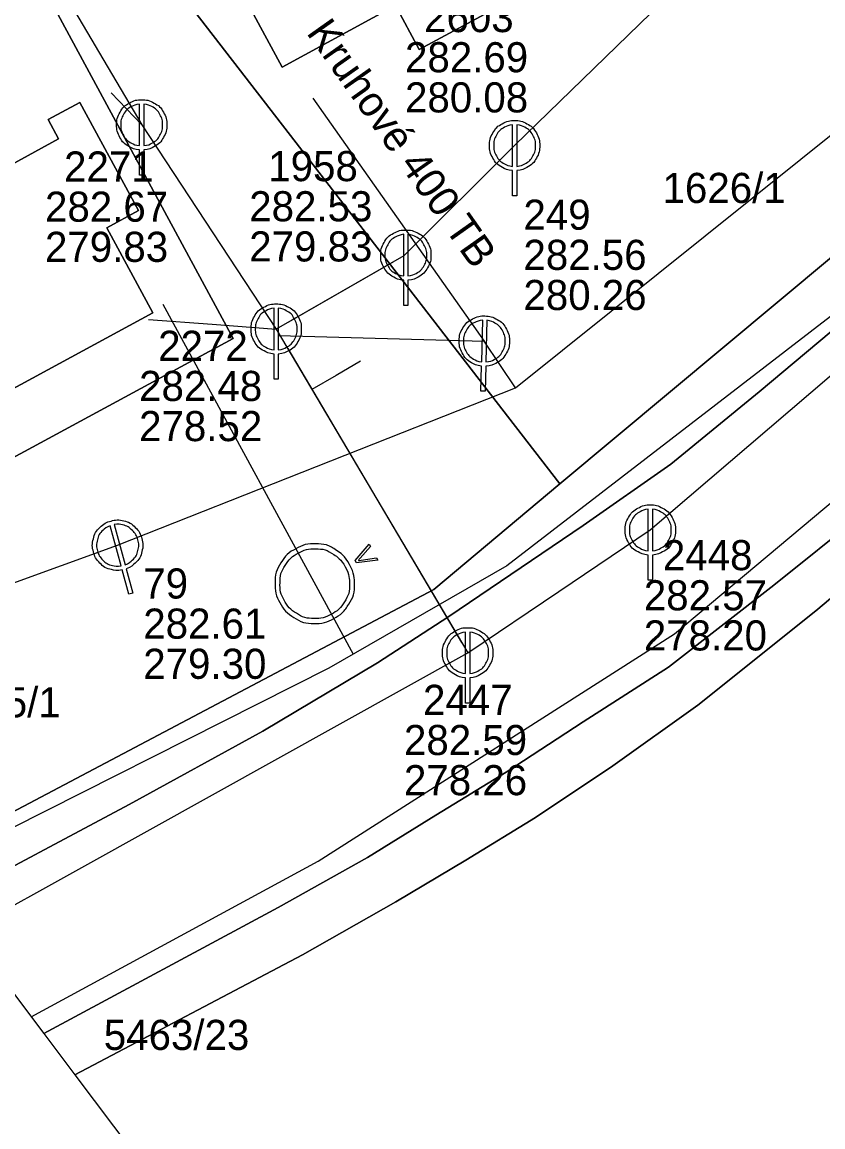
# Model space of a CAD drawing. Extents: x -570698 to -570232, y -1086952 to -1086596.
# Drawn here: x -570540.7 to -570500.8, y -1086880.7 to -1086825.7 of the extents above; entities that cross this region are included whole.
import ezdxf

# ---------------------------------------------------------------- set-up
doc = ezdxf.new("R2010")
doc.units = 0
for name, color, linetype in [('Chránička - kanalizace', 7, 'Continuous'), ('Default', 7, 'Continuous'), ('Kanalizační přípojka', 7, 'Continuous'), ('Kanalizační stoka', 7, 'Continuous'), ('Kanalizační šachta', 7, 'Continuous'), ('Parcela-polygon', 7, 'Continuous'), ('Parcela-text', 7, 'Continuous'), ('Popis kmenové stoky', 7, 'Continuous'), ('Popis šachty', 7, 'Continuous'), ('Vodovodní přípojka', 7, 'Continuous'), ('Vodovodní řad', 7, 'Continuous'), ('Vodovodní šachta', 7, 'Continuous')]:
    doc.layers.add(name, color=color, linetype=linetype)

msp = doc.modelspace()

# ---------------------------------------------------------------- linework, layer by layer
at = {"layer": 'Chránička - kanalizace'}
for points in [[(-570522.159, -1086837.647), (-570527.394, -1086840.643)], [(-570527.425, -1086841.962), (-570518.762, -1086856.609)]]:
    msp.add_lwpolyline(points, dxfattribs=at)
at = {"layer": 'Default'}
for points in [[(-570534.803, -1086832.068), (-570535.061, -1086832.05), (-570535.323, -1086831.904), (-570535.62, -1086831.74), (-570535.785, -1086831.443), (-570535.95, -1086831.145), (-570535.95, -1086830.82), (-570535.95, -1086830.493), (-570535.782, -1086830.193), (-570535.613, -1086829.892), (-570535.315, -1086829.731), (-570535.017, -1086829.57), (-570534.7, -1086829.57), (-570534.385, -1086829.57), (-570534.086, -1086829.731), (-570533.787, -1086829.892), (-570533.618, -1086830.193), (-570533.45, -1086830.493), (-570533.45, -1086830.82), (-570533.45, -1086831.145), (-570533.615, -1086831.443), (-570533.78, -1086831.74), (-570534.077, -1086831.904), (-570534.339, -1086832.05), (-570534.597, -1086832.068)], [(-570534.803, -1086829.782), (-570535, -1086829.799), (-570535.215, -1086829.914), (-570535.464, -1086830.049), (-570535.603, -1086830.299), (-570535.742, -1086830.549), (-570535.742, -1086830.82), (-570535.742, -1086831.091), (-570535.606, -1086831.338), (-570535.469, -1086831.584), (-570535.22, -1086831.721), (-570535.008, -1086831.841), (-570534.803, -1086831.855)], [(-570534.597, -1086831.855), (-570534.392, -1086831.841), (-570534.178, -1086831.721), (-570533.931, -1086831.584), (-570533.794, -1086831.338), (-570533.658, -1086831.091), (-570533.658, -1086830.82), (-570533.658, -1086830.549), (-570533.798, -1086830.299), (-570533.938, -1086830.049), (-570534.187, -1086829.914), (-570534.4, -1086829.799), (-570534.597, -1086829.782)], [(-570516.223, -1086833.098), (-570516.481, -1086833.08), (-570516.743, -1086832.934), (-570517.04, -1086832.77), (-570517.205, -1086832.473), (-570517.37, -1086832.175), (-570517.37, -1086831.85), (-570517.37, -1086831.523), (-570517.202, -1086831.223), (-570517.033, -1086830.922), (-570516.735, -1086830.761), (-570516.437, -1086830.6), (-570516.12, -1086830.6), (-570515.805, -1086830.6), (-570515.506, -1086830.761), (-570515.207, -1086830.922), (-570515.038, -1086831.223), (-570514.87, -1086831.523), (-570514.87, -1086831.85), (-570514.87, -1086832.175), (-570515.035, -1086832.473), (-570515.2, -1086832.77), (-570515.497, -1086832.934), (-570515.759, -1086833.08), (-570516.017, -1086833.098)], [(-570516.223, -1086830.812), (-570516.42, -1086830.829), (-570516.635, -1086830.944), (-570516.884, -1086831.079), (-570517.023, -1086831.329), (-570517.162, -1086831.579), (-570517.162, -1086831.85), (-570517.162, -1086832.121), (-570517.026, -1086832.368), (-570516.889, -1086832.614), (-570516.64, -1086832.751), (-570516.428, -1086832.871), (-570516.223, -1086832.885)], [(-570516.017, -1086832.885), (-570515.812, -1086832.871), (-570515.598, -1086832.751), (-570515.351, -1086832.614), (-570515.214, -1086832.368), (-570515.078, -1086832.121), (-570515.078, -1086831.85), (-570515.078, -1086831.579), (-570515.218, -1086831.329), (-570515.358, -1086831.079), (-570515.607, -1086830.944), (-570515.82, -1086830.829), (-570516.017, -1086830.812)], [(-570521.643, -1086838.558), (-570521.901, -1086838.54), (-570522.163, -1086838.394), (-570522.46, -1086838.23), (-570522.625, -1086837.933), (-570522.79, -1086837.635), (-570522.79, -1086837.31), (-570522.79, -1086836.983), (-570522.622, -1086836.683), (-570522.453, -1086836.382), (-570522.155, -1086836.221), (-570521.857, -1086836.06), (-570521.54, -1086836.06), (-570521.225, -1086836.06), (-570520.926, -1086836.221), (-570520.627, -1086836.382), (-570520.458, -1086836.683), (-570520.29, -1086836.983), (-570520.29, -1086837.31), (-570520.29, -1086837.635), (-570520.455, -1086837.933), (-570520.62, -1086838.23), (-570520.917, -1086838.394), (-570521.179, -1086838.54), (-570521.437, -1086838.558)], [(-570521.643, -1086836.272), (-570521.84, -1086836.289), (-570522.055, -1086836.404), (-570522.304, -1086836.539), (-570522.443, -1086836.789), (-570522.582, -1086837.039), (-570522.582, -1086837.31), (-570522.582, -1086837.581), (-570522.446, -1086837.828), (-570522.309, -1086838.074), (-570522.06, -1086838.211), (-570521.848, -1086838.331), (-570521.643, -1086838.345)], [(-570521.437, -1086838.345), (-570521.232, -1086838.331), (-570521.018, -1086838.211), (-570520.771, -1086838.074), (-570520.634, -1086837.828), (-570520.498, -1086837.581), (-570520.498, -1086837.31), (-570520.498, -1086837.039), (-570520.638, -1086836.789), (-570520.778, -1086836.539), (-570521.027, -1086836.404), (-570521.24, -1086836.289), (-570521.437, -1086836.272)], [(-570528.103, -1086842.238), (-570528.361, -1086842.22), (-570528.623, -1086842.074), (-570528.92, -1086841.91), (-570529.085, -1086841.613), (-570529.25, -1086841.315), (-570529.25, -1086840.99), (-570529.25, -1086840.663), (-570529.082, -1086840.363), (-570528.913, -1086840.062), (-570528.615, -1086839.901), (-570528.317, -1086839.74), (-570528, -1086839.74), (-570527.685, -1086839.74), (-570527.386, -1086839.901), (-570527.087, -1086840.062), (-570526.918, -1086840.363), (-570526.75, -1086840.663), (-570526.75, -1086840.99), (-570526.75, -1086841.315), (-570526.915, -1086841.613), (-570527.08, -1086841.91), (-570527.377, -1086842.074), (-570527.639, -1086842.22), (-570527.897, -1086842.238)], [(-570528.103, -1086839.952), (-570528.3, -1086839.969), (-570528.515, -1086840.084), (-570528.764, -1086840.219), (-570528.903, -1086840.469), (-570529.042, -1086840.719), (-570529.042, -1086840.99), (-570529.042, -1086841.261), (-570528.906, -1086841.508), (-570528.769, -1086841.754), (-570528.52, -1086841.891), (-570528.308, -1086842.011), (-570528.103, -1086842.025)], [(-570527.897, -1086842.025), (-570527.692, -1086842.011), (-570527.478, -1086841.891), (-570527.231, -1086841.754), (-570527.094, -1086841.508), (-570526.958, -1086841.261), (-570526.958, -1086840.99), (-570526.958, -1086840.719), (-570527.098, -1086840.469), (-570527.238, -1086840.219), (-570527.487, -1086840.084), (-570527.7, -1086839.969), (-570527.897, -1086839.952)], [(-570517.766, -1086842.834), (-570518.024, -1086842.81), (-570518.281, -1086842.657), (-570518.575, -1086842.485), (-570518.732, -1086842.183), (-570518.888, -1086841.881), (-570518.88, -1086841.556), (-570518.871, -1086841.229), (-570518.695, -1086840.934), (-570518.518, -1086840.638), (-570518.216, -1086840.485), (-570517.914, -1086840.332), (-570517.597, -1086840.34), (-570517.282, -1086840.348), (-570516.987, -1086840.518), (-570516.693, -1086840.687), (-570516.532, -1086840.991), (-570516.372, -1086841.296), (-570516.381, -1086841.623), (-570516.389, -1086841.948), (-570516.562, -1086842.241), (-570516.735, -1086842.534), (-570517.037, -1086842.69), (-570517.302, -1086842.829), (-570517.561, -1086842.839)], [(-570517.705, -1086840.55), (-570517.903, -1086840.561), (-570518.121, -1086840.67), (-570518.373, -1086840.798), (-570518.519, -1086841.044), (-570518.665, -1086841.291), (-570518.672, -1086841.562), (-570518.679, -1086841.833), (-570518.549, -1086842.083), (-570518.419, -1086842.333), (-570518.174, -1086842.476), (-570517.965, -1086842.602), (-570517.76, -1086842.622)], [(-570517.555, -1086842.627), (-570517.35, -1086842.618), (-570517.132, -1086842.504), (-570516.882, -1086842.374), (-570516.739, -1086842.131), (-570516.595, -1086841.888), (-570516.588, -1086841.617), (-570516.581, -1086841.347), (-570516.714, -1086841.093), (-570516.848, -1086840.839), (-570517.093, -1086840.698), (-570517.303, -1086840.578), (-570517.5, -1086840.555)], [(-570509.463, -1086852.248), (-570509.721, -1086852.23), (-570509.983, -1086852.084), (-570510.28, -1086851.92), (-570510.445, -1086851.623), (-570510.61, -1086851.325), (-570510.61, -1086851), (-570510.61, -1086850.673), (-570510.442, -1086850.373), (-570510.273, -1086850.072), (-570509.975, -1086849.911), (-570509.677, -1086849.75), (-570509.36, -1086849.75), (-570509.045, -1086849.75), (-570508.746, -1086849.911), (-570508.447, -1086850.072), (-570508.278, -1086850.373), (-570508.11, -1086850.673), (-570508.11, -1086851), (-570508.11, -1086851.325), (-570508.275, -1086851.623), (-570508.44, -1086851.92), (-570508.737, -1086852.084), (-570508.999, -1086852.23), (-570509.257, -1086852.248)], [(-570509.463, -1086849.962), (-570509.66, -1086849.979), (-570509.875, -1086850.094), (-570510.124, -1086850.229), (-570510.263, -1086850.479), (-570510.402, -1086850.729), (-570510.402, -1086851), (-570510.402, -1086851.271), (-570510.266, -1086851.518), (-570510.129, -1086851.764), (-570509.88, -1086851.901), (-570509.668, -1086852.021), (-570509.463, -1086852.035)], [(-570509.257, -1086852.035), (-570509.052, -1086852.021), (-570508.838, -1086851.901), (-570508.591, -1086851.764), (-570508.454, -1086851.518), (-570508.318, -1086851.271), (-570508.318, -1086851), (-570508.318, -1086850.729), (-570508.458, -1086850.479), (-570508.598, -1086850.229), (-570508.847, -1086850.094), (-570509.06, -1086849.979), (-570509.257, -1086849.962)], [(-570535.671, -1086852.99), (-570535.925, -1086853.042), (-570536.216, -1086852.969), (-570536.546, -1086852.89), (-570536.783, -1086852.646), (-570537.021, -1086852.402), (-570537.106, -1086852.088), (-570537.192, -1086851.773), (-570537.109, -1086851.439), (-570537.025, -1086851.105), (-570536.78, -1086850.871), (-570536.535, -1086850.637), (-570536.229, -1086850.554), (-570535.925, -1086850.471), (-570535.594, -1086850.548), (-570535.263, -1086850.625), (-570535.021, -1086850.87), (-570534.78, -1086851.116), (-570534.694, -1086851.431), (-570534.609, -1086851.744), (-570534.689, -1086852.075), (-570534.77, -1086852.406), (-570535.014, -1086852.642), (-570535.228, -1086852.852), (-570535.473, -1086852.936)], [(-570536.272, -1086850.786), (-570536.458, -1086850.854), (-570536.635, -1086851.021), (-570536.84, -1086851.216), (-570536.909, -1086851.494), (-570536.977, -1086851.772), (-570536.906, -1086852.034), (-570536.835, -1086852.295), (-570536.638, -1086852.497), (-570536.441, -1086852.699), (-570536.165, -1086852.766), (-570535.929, -1086852.825), (-570535.727, -1086852.785)], [(-570535.529, -1086852.732), (-570535.335, -1086852.664), (-570535.159, -1086852.492), (-570534.957, -1086852.295), (-570534.89, -1086852.021), (-570534.823, -1086851.747), (-570534.894, -1086851.486), (-570534.965, -1086851.224), (-570535.167, -1086851.02), (-570535.368, -1086850.815), (-570535.643, -1086850.751), (-570535.879, -1086850.696), (-570536.074, -1086850.732)], [(-570524.34, -1086852.724), (-570524.101, -1086853.162), (-570524.099, -1086853.7), (-570524.096, -1086854.237), (-570524.387, -1086854.701), (-570524.677, -1086855.164), (-570525.134, -1086855.412), (-570525.584, -1086855.657), (-570526.122, -1086855.652), (-570526.66, -1086855.647), (-570527.115, -1086855.358), (-570527.57, -1086855.068), (-570527.817, -1086854.615), (-570528.06, -1086854.168), (-570528.056, -1086853.628), (-570528.051, -1086853.089), (-570527.763, -1086852.635), (-570527.475, -1086852.18), (-570527.025, -1086851.935), (-570526.569, -1086851.687), (-570526.023, -1086851.692), (-570525.478, -1086851.697), (-570525.028, -1086851.991), (-570524.578, -1086852.285), (-570524.34, -1086852.724)], [(-570524.556, -1086852.841), (-570524.763, -1086852.46), (-570525.158, -1086852.202), (-570525.553, -1086851.944), (-570526.031, -1086851.939), (-570526.508, -1086851.934), (-570526.907, -1086852.152), (-570527.301, -1086852.366), (-570527.553, -1086852.764), (-570527.806, -1086853.162), (-570527.81, -1086853.633), (-570527.814, -1086854.104), (-570527.6, -1086854.497), (-570527.383, -1086854.897), (-570526.985, -1086855.149), (-570526.587, -1086855.401), (-570526.116, -1086855.406), (-570525.645, -1086855.41), (-570525.251, -1086855.196), (-570524.852, -1086854.979), (-570524.599, -1086854.573), (-570524.345, -1086854.166), (-570524.346, -1086853.696), (-570524.347, -1086853.226), (-570524.556, -1086852.841)], [(-570523.82, -1086852.406), (-570523.883, -1086852.476), (-570523.939, -1086852.529), (-570523.856, -1086852.511), (-570523.769, -1086852.499)], [(-570518.563, -1086858.368), (-570518.821, -1086858.35), (-570519.083, -1086858.204), (-570519.38, -1086858.04), (-570519.545, -1086857.743), (-570519.71, -1086857.445), (-570519.71, -1086857.12), (-570519.71, -1086856.793), (-570519.542, -1086856.493), (-570519.373, -1086856.192), (-570519.075, -1086856.031), (-570518.777, -1086855.87), (-570518.46, -1086855.87), (-570518.145, -1086855.87), (-570517.846, -1086856.031), (-570517.547, -1086856.192), (-570517.378, -1086856.493), (-570517.21, -1086856.793), (-570517.21, -1086857.12), (-570517.21, -1086857.445), (-570517.375, -1086857.743), (-570517.54, -1086858.04), (-570517.837, -1086858.204), (-570518.099, -1086858.35), (-570518.357, -1086858.368)], [(-570518.563, -1086856.082), (-570518.76, -1086856.099), (-570518.975, -1086856.214), (-570519.224, -1086856.349), (-570519.363, -1086856.599), (-570519.502, -1086856.849), (-570519.502, -1086857.12), (-570519.502, -1086857.391), (-570519.366, -1086857.638), (-570519.229, -1086857.884), (-570518.98, -1086858.021), (-570518.768, -1086858.141), (-570518.563, -1086858.155)], [(-570518.357, -1086858.155), (-570518.152, -1086858.141), (-570517.938, -1086858.021), (-570517.691, -1086857.884), (-570517.554, -1086857.638), (-570517.418, -1086857.391), (-570517.418, -1086857.12), (-570517.418, -1086856.849), (-570517.558, -1086856.599), (-570517.698, -1086856.349), (-570517.947, -1086856.214), (-570518.16, -1086856.099), (-570518.357, -1086856.082)]]:
    msp.add_open_spline(points, degree=3, dxfattribs=at)
at = {"layer": 'Kanalizační přípojka'}
msp.add_line((-570527.889, -1086841.316), (-570517.63, -1086841.59), dxfattribs=at)
for points in [[(-570536.216, -1086829.226), (-570534.7, -1086830.82)], [(-570534.368, -1086840.516), (-570531.184, -1086840.753), (-570528, -1086840.99)], [(-570523.8, -1086842.59), (-570525.009, -1086843.296), (-570526.218, -1086844.003)]]:
    msp.add_lwpolyline(points, dxfattribs=at)
at = {"layer": 'Kanalizační stoka'}
for p, q in [((-570516.073, -1086843.915), (-570416.01, -1086763.66)), ((-570535.9, -1086851.76), (-570516.073, -1086843.915))]:
    msp.add_line(p, q, dxfattribs=at)
for points in [[(-570500.84, -1086817), (-570516.12, -1086831.85)], [(-570539.34, -1086822.925), (-570534.7, -1086830.82)], [(-570509.36, -1086851), (-570496.445, -1086839.955), (-570483.53, -1086828.91)], [(-570526.18, -1086829.489), (-570517.63, -1086841.59)], [(-570534.7, -1086830.82), (-570528, -1086840.99)], [(-570516.12, -1086831.85), (-570521.64, -1086837.35)], [(-570521.64, -1086837.35), (-570528, -1086840.99)], [(-570528, -1086840.99), (-570518.46, -1086857.12)], [(-570516.073, -1086843.915), (-570517.63, -1086841.59)], [(-570518.46, -1086857.12), (-570513.91, -1086854.06), (-570509.36, -1086851)], [(-570553.189, -1086858.005), (-570553.028, -1086857.971), (-570535.9, -1086851.76)], [(-570543.41, -1086870.991), (-570537.535, -1086867.725), (-570518.46, -1086857.12)]]:
    msp.add_lwpolyline(points, dxfattribs=at)
at = {"layer": 'Kanalizační šachta'}
for points in [[(-570534.803, -1086831.855), (-570534.803, -1086829.782)], [(-570534.597, -1086829.782), (-570534.597, -1086831.855)], [(-570516.223, -1086832.885), (-570516.223, -1086830.812)], [(-570516.017, -1086830.812), (-570516.017, -1086832.885)], [(-570534.597, -1086832.068), (-570534.597, -1086833.32), (-570534.803, -1086833.32), (-570534.803, -1086832.068)], [(-570516.017, -1086833.098), (-570516.017, -1086834.35), (-570516.223, -1086834.35), (-570516.223, -1086833.098)], [(-570521.643, -1086838.345), (-570521.643, -1086836.272)], [(-570521.437, -1086836.272), (-570521.437, -1086838.345)], [(-570521.437, -1086838.558), (-570521.437, -1086839.81), (-570521.643, -1086839.81), (-570521.643, -1086838.558)], [(-570528.103, -1086842.025), (-570528.103, -1086839.952)], [(-570527.897, -1086839.952), (-570527.897, -1086842.025)], [(-570517.76, -1086842.622), (-570517.705, -1086840.55)], [(-570517.5, -1086840.555), (-570517.555, -1086842.627)], [(-570527.897, -1086842.238), (-570527.897, -1086843.49), (-570528.103, -1086843.49), (-570528.103, -1086842.238)], [(-570517.561, -1086842.839), (-570517.594, -1086844.091), (-570517.799, -1086844.086), (-570517.766, -1086842.834)], [(-570509.463, -1086852.035), (-570509.463, -1086849.962)], [(-570509.257, -1086849.962), (-570509.257, -1086852.035)], [(-570535.727, -1086852.785), (-570536.272, -1086850.786)], [(-570536.074, -1086850.732), (-570535.529, -1086852.732)], [(-570509.257, -1086852.248), (-570509.257, -1086853.5), (-570509.463, -1086853.5), (-570509.463, -1086852.248)], [(-570535.473, -1086852.936), (-570535.144, -1086854.145), (-570535.342, -1086854.199), (-570535.671, -1086852.99)], [(-570518.563, -1086858.155), (-570518.563, -1086856.082)], [(-570518.357, -1086856.082), (-570518.357, -1086858.155)], [(-570518.357, -1086858.368), (-570518.357, -1086859.62), (-570518.563, -1086859.62), (-570518.563, -1086858.368)]]:
    msp.add_lwpolyline(points, dxfattribs=at)
at = {"layer": 'Parcela-polygon'}
for p, q in [((-570544.494, -1086869.551), (-570539.571, -1086876.089)), ((-570539.571, -1086876.089), (-570538.024, -1086878.143)), ((-570538.024, -1086878.143), (-570507.088, -1086919.226))]:
    msp.add_line(p, q, dxfattribs=at)
for points in [[(-570291.64, -1086688.892), (-570302.37, -1086696.04), (-570396.95, -1086758.9), (-570417.85, -1086767.9), (-570426.99, -1086775.07), (-570430.55, -1086777.63), (-570432.81, -1086779.33), (-570437.1, -1086782.56), (-570450.62, -1086793.64), (-570452.87, -1086797.51), (-570456.3, -1086803.42), (-570469.27, -1086814.47), (-570499.22, -1086840.17), (-570503.94, -1086844.12), (-570508.33, -1086847.72), (-570512.7, -1086850.77), (-570519.4, -1086855.31), (-570522.96, -1086857.62), (-570528.66, -1086861.02), (-570535.32, -1086864.67), (-570544.494, -1086869.551)], [(-570544.494, -1086869.551), (-570535.32, -1086864.67), (-570528.66, -1086861.02), (-570522.96, -1086857.62), (-570519.4, -1086855.31), (-570512.7, -1086850.77), (-570508.33, -1086847.72), (-570503.94, -1086844.12), (-570499.22, -1086840.17), (-570469.27, -1086814.47), (-570456.3, -1086803.42), (-570452.87, -1086797.51), (-570485.9, -1086825.32), (-570492.12, -1086830.55), (-570513.86, -1086848.7), (-570520.15, -1086853.96), (-570542.94, -1086866), (-570545.975, -1086867.584)], [(-570545.975, -1086867.584), (-570542.94, -1086866), (-570520.15, -1086853.96), (-570513.86, -1086848.7), (-570535.84, -1086820.27), (-570533.06, -1086818.87), (-570537.68, -1086810.96), (-570547, -1086816.06), (-570542.59, -1086823.97), (-570540.28, -1086822.7), (-570540.19, -1086822.86), (-570530.15, -1086841.46), (-570555.373, -1086855.104)], [(-570539.571, -1086876.089), (-570527.9, -1086869.8), (-570523.45, -1086867.31), (-570520.05, -1086865.2), (-570516.55, -1086863.06), (-570512.7, -1086860.56), (-570508.46, -1086857.83), (-570503.21, -1086853.75), (-570498.77, -1086850.2), (-570494.11, -1086846.18), (-570471.26, -1086826.6), (-570461.73, -1086819.28)], [(-570555.373, -1086855.104), (-570530.15, -1086841.46), (-570540.19, -1086822.86), (-570540.28, -1086822.7), (-570542.59, -1086823.97), (-570568.236, -1086838.021)], [(-570538.024, -1086878.143), (-570526.69, -1086872.16), (-570522.04, -1086869.52), (-570518.55, -1086867.44), (-570515.08, -1086865.32), (-570511.23, -1086862.75), (-570507, -1086859.73), (-570501.11, -1086855.03), (-570492.56, -1086847.83), (-570466.87, -1086826.17), (-570468.82, -1086825.8), (-570470.31, -1086826.04), (-570471.26, -1086826.6), (-570494.11, -1086846.18), (-570498.77, -1086850.2), (-570503.21, -1086853.75), (-570508.46, -1086857.83), (-570512.7, -1086860.56), (-570516.55, -1086863.06), (-570520.05, -1086865.2), (-570523.45, -1086867.31), (-570527.9, -1086869.8), (-570539.571, -1086876.089)], [(-570557.2, -1086852.678), (-570534.15, -1086840.19), (-570536.44, -1086835.95), (-570534.86, -1086835.09), (-570537.78, -1086829.7), (-570539.36, -1086830.56), (-570538.84, -1086831.52), (-570547.11, -1086836.05), (-570547.31, -1086835.68), (-570549.98, -1086837.14), (-570549.78, -1086837.51), (-570560.59, -1086843.43), (-570560.8, -1086843.06), (-570563.377, -1086844.474)], [(-570563.377, -1086844.474), (-570560.8, -1086843.06), (-570560.59, -1086843.43), (-570549.78, -1086837.51), (-570549.98, -1086837.14), (-570547.31, -1086835.68), (-570547.11, -1086836.05), (-570538.84, -1086831.52), (-570539.36, -1086830.56), (-570537.78, -1086829.7), (-570534.86, -1086835.09), (-570536.44, -1086835.95), (-570534.15, -1086840.19), (-570557.2, -1086852.678)], [(-570507.088, -1086919.226), (-570487.55, -1086900.19), (-570485.3, -1086902.53), (-570483.34, -1086904.56), (-570467.38, -1086889.2), (-570492.56, -1086847.83), (-570501.11, -1086855.03), (-570507, -1086859.73), (-570511.23, -1086862.75), (-570515.08, -1086865.32), (-570518.55, -1086867.44), (-570522.04, -1086869.52), (-570526.69, -1086872.16), (-570538.024, -1086878.143)]]:
    msp.add_lwpolyline(points, dxfattribs=at)
for points in [[(-570513.7, -1086820.33), (-570504.9, -1086815.55), (-570509.92, -1086806.32), (-570516.59, -1086809.94), (-570517.3, -1086808.64), (-570525.69, -1086813.18), (-570524.97, -1086814.49), (-570532.7, -1086818.69), (-570527.71, -1086827.94), (-570522.06, -1086824.88), (-570520.87, -1086827.06), (-570517.39, -1086825.19), (-570518.59, -1086822.99), (-570516.47, -1086821.84), (-570516.4, -1086821.96), (-570513.63, -1086820.46)], [(-570494.84, -1086825), (-570495.06, -1086824.55), (-570499.45, -1086815.57), (-570501.22, -1086816.39), (-570502.28, -1086814.13), (-570504.9, -1086815.55), (-570513.7, -1086820.33), (-570513.63, -1086820.46), (-570516.4, -1086821.96), (-570516.47, -1086821.84), (-570518.59, -1086822.99), (-570517.39, -1086825.19), (-570520.87, -1086827.06), (-570522.06, -1086824.88), (-570527.71, -1086827.94), (-570532.7, -1086818.69), (-570533.06, -1086818.87), (-570535.84, -1086820.27), (-570513.86, -1086848.7), (-570492.12, -1086830.55)]]:
    msp.add_lwpolyline(points, close=True, dxfattribs=at)
at = {"layer": 'Vodovodní přípojka'}
msp.add_line((-570533.65, -1086839.748), (-570524.167, -1086857.183), dxfattribs=at)
at = {"layer": 'Vodovodní řad'}
for points in [[(-570429.328, -1086757.943), (-570424.039, -1086777.75), (-570480.425, -1086822.995), (-570494.455, -1086835.799), (-570516.511, -1086852.784), (-570525.384, -1086857.882), (-570544.749, -1086867.64), (-570545.576, -1086868.114)], [(-570540.206, -1086875.246), (-570525.908, -1086867.498), (-570508.157, -1086856.172), (-570464.866, -1086819.881), (-570444.41, -1086803.214)]]:
    msp.add_lwpolyline(points, dxfattribs=at)
at = {"layer": 'Vodovodní šachta'}
for points in [[(-570524.071, -1086852.523), (-570523.375, -1086851.701), (-570523.306, -1086851.827), (-570523.82, -1086852.406)], [(-570523.769, -1086852.499), (-570523.001, -1086852.388), (-570522.935, -1086852.509), (-570524.006, -1086852.643), (-570524.071, -1086852.523)]]:
    msp.add_lwpolyline(points, dxfattribs=at)

# ---------------------------------------------------------------- texts
at = {"layer": 'Parcela-text'}
for s, p in [('1626/1', (-570508.75, -1086834.71)), ('1625/1', (-570544.87, -1086860.33)), ('5463/23', (-570536.59, -1086876.9))]:
    msp.add_text(s, height=1.5, dxfattribs=at).set_placement(p)
at = {"layer": 'Popis kmenové stoky'}
msp.add_text('Kruhové 400 TB', height=1.5, rotation=305.2432, dxfattribs=at).set_placement((-570526.527, -1086826.232))
at = {"layer": 'Popis šachty'}
for s, p in [('2603', (-570520.631, -1086826.2)), ('282.69', (-570521.581, -1086828.2)), ('280.08', (-570521.581, -1086830.2)), ('2271', (-570538.568, -1086833.644)), ('1958', (-570528.394, -1086833.624)), ('282.67', (-570539.518, -1086835.644)), ('282.53', (-570529.343, -1086835.624)), ('249', (-570515.681, -1086836.043)), ('279.83', (-570539.518, -1086837.644)), ('279.83', (-570529.343, -1086837.624)), ('282.56', (-570515.681, -1086838.043)), ('280.26', (-570515.681, -1086840.043)), ('2272', (-570533.879, -1086842.574)), ('282.48', (-570534.829, -1086844.574)), ('278.52', (-570534.829, -1086846.574)), ('2448', (-570508.734, -1086853.002)), ('79', (-570534.622, -1086854.414)), ('282.57', (-570509.683, -1086855.002)), ('282.61', (-570534.622, -1086856.414)), ('278.20', (-570509.683, -1086857.002)), ('279.30', (-570534.622, -1086858.414)), ('2447', (-570520.684, -1086860.211)), ('282.59', (-570521.633, -1086862.211)), ('278.26', (-570521.633, -1086864.211))]:
    msp.add_text(s, height=1.5, dxfattribs=at).set_placement(p)

doc.saveas('drawing.dxf')
